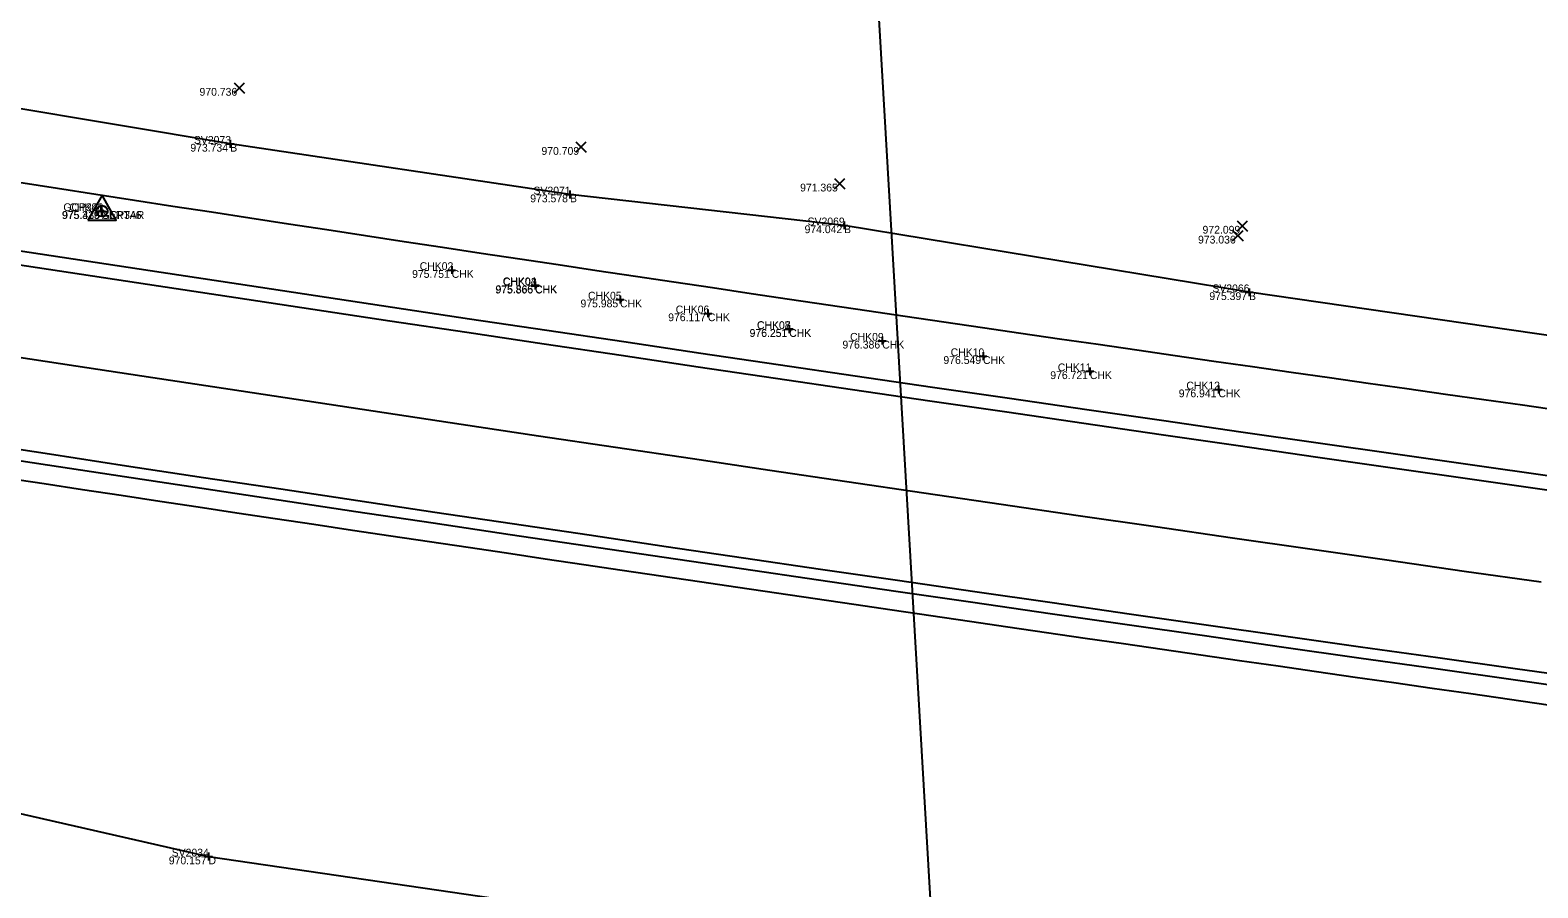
# Model space of a CAD drawing. Extents: x 2065431 to 2068157, y 709104 to 709719.
# Drawn here: x 2066286.8 to 2066480.2, y 709483.7 to 709593.7 of the extents above; entities that cross this region are included whole.
import ezdxf

# ---------------------------------------------------------------- set-up
doc = ezdxf.new("R2010")
doc.units = 0
for name, color, linetype in [('DR_X_Storm_Sewer', 7, 'Continuous'), ('PM_X_Edge_Line', 7, 'Continuous'), ('PM_X_Lane_Line', 7, 'Continuous'), ('PV_X_EOP', 7, 'Continuous'), ('PV_X_Shoulder_Rumble_Strip', 7, 'Continuous'), ('RS_Raster1', 7, 'Continuous'), ('RW_X_CL_100_Bearings', 7, 'Continuous'), ('RW_X_Fee_WL', 7, 'Continuous'), ('SV_P_Aerial_Targets', 7, 'Continuous'), ('SV_X_Break_Lines', 7, 'Continuous'), ('SV_X_Mon_Cells_Found', 7, 'Continuous'), ('SV_X_Text_Elevation', 7, 'Continuous'), ('SV_X_Text_Name', 7, 'Continuous')]:
    doc.layers.add(name, color=color, linetype=linetype)

msp = doc.modelspace()

# ---------------------------------------------------------------- linework, layer by layer
at = {"layer": 'DR_X_Storm_Sewer'}
msp.add_line((2066393.36, 709634.39), (2066412.21, 709311.61), dxfattribs=at)
at = {"layer": 'PM_X_Edge_Line'}
for points in [[(2066283.48, 709563.93), (2066293.37, 709562.43), (2066303.26, 709560.93), (2066313.15, 709559.43), (2066323.03, 709557.95), (2066332.92, 709556.46), (2066342.81, 709554.98), (2066352.7, 709553.51), (2066362.6, 709552.04), (2066372.49, 709550.57), (2066382.38, 709549.11), (2066392.27, 709547.66), (2066402.17, 709546.2), (2066412.06, 709544.76), (2066421.96, 709543.32), (2066431.85, 709541.88), (2066441.75, 709540.45), (2066451.65, 709539.02), (2066461.55, 709537.6), (2066471.45, 709536.18), (2066481.35, 709534.77)], [(2066279.38, 709540.88), (2066289.26, 709539.37), (2066299.15, 709537.87), (2066309.04, 709536.37), (2066318.93, 709534.88), (2066328.81, 709533.39), (2066338.7, 709531.92), (2066348.6, 709530.44), (2066358.49, 709528.98), (2066368.38, 709527.51), (2066378.27, 709526.06), (2066388.17, 709524.61), (2066398.06, 709523.17), (2066407.96, 709521.73), (2066417.86, 709520.3), (2066427.76, 709518.88), (2066437.65, 709517.46), (2066447.55, 709516.05), (2066457.45, 709514.65), (2066467.36, 709513.25), (2066477.26, 709511.86), (2066487.16, 709510.47)]]:
    msp.add_lwpolyline(points, dxfattribs=at)
at = {"layer": 'PM_X_Lane_Line'}
msp.add_lwpolyline([(2066282.76, 709552.18), (2066292.65, 709550.67), (2066302.53, 709549.17), (2066312.42, 709547.67), (2066322.31, 709546.17), (2066332.2, 709544.68), (2066342.09, 709543.2), (2066351.98, 709541.72), (2066361.87, 709540.24), (2066371.76, 709538.78), (2066381.65, 709537.31), (2066391.54, 709535.85), (2066401.44, 709534.4), (2066411.33, 709532.95), (2066421.23, 709531.5), (2066431.12, 709530.07), (2066441.02, 709528.63), (2066450.92, 709527.2), (2066460.81, 709525.78), (2066470.71, 709524.36), (2066480.61, 709522.95)], dxfattribs=at)
at = {"layer": 'PV_X_EOP'}
for points in [[(2066285.33, 709574.24), (2066290.27, 709573.47), (2066295.21, 709572.7), (2066300.15, 709571.94), (2066305.09, 709571.18), (2066310.04, 709570.42), (2066314.98, 709569.66), (2066319.92, 709568.91), (2066324.86, 709568.15), (2066329.81, 709567.4), (2066334.75, 709566.65), (2066339.69, 709565.9), (2066344.64, 709565.15), (2066349.58, 709564.41), (2066354.53, 709563.66), (2066359.47, 709562.92), (2066364.42, 709562.18), (2066369.36, 709561.44), (2066374.31, 709560.71), (2066379.25, 709559.97), (2066384.2, 709559.24), (2066389.14, 709558.51), (2066394.09, 709557.78), (2066399.04, 709557.05), (2066403.99, 709556.33), (2066408.93, 709555.6), (2066413.88, 709554.88), (2066418.83, 709554.16), (2066423.78, 709553.44), (2066428.72, 709552.73), (2066433.67, 709552.01), (2066438.62, 709551.3), (2066443.57, 709550.59), (2066448.52, 709549.88), (2066453.47, 709549.17), (2066458.42, 709548.47), (2066463.37, 709547.76), (2066468.32, 709547.06), (2066473.27, 709546.36), (2066478.22, 709545.66), (2066483.17, 709544.96)], [(2066283.62, 709536.32), (2066288.56, 709535.57), (2066293.51, 709534.82), (2066298.45, 709534.07), (2066303.4, 709533.33), (2066308.34, 709532.58), (2066313.29, 709531.84), (2066318.23, 709531.1), (2066323.17, 709530.36), (2066328.12, 709529.62), (2066333.06, 709528.88), (2066338.01, 709528.14), (2066342.96, 709527.4), (2066347.9, 709526.67), (2066352.85, 709525.93), (2066357.79, 709525.2), (2066362.74, 709524.47), (2066367.68, 709523.74), (2066372.63, 709523.01), (2066377.58, 709522.28), (2066382.52, 709521.55), (2066387.47, 709520.82), (2066392.42, 709520.1), (2066397.37, 709519.37), (2066402.31, 709518.65), (2066407.26, 709517.92), (2066412.21, 709517.2), (2066417.16, 709516.48), (2066422.1, 709515.76), (2066427.05, 709515.04), (2066432, 709514.33), (2066436.95, 709513.61), (2066441.9, 709512.89), (2066446.85, 709512.18), (2066451.79, 709511.47), (2066456.74, 709510.76), (2066461.69, 709510.04), (2066466.64, 709509.33), (2066471.59, 709508.63), (2066476.54, 709507.92), (2066481.49, 709507.21)]]:
    msp.add_lwpolyline(points, dxfattribs=at)
at = {"layer": 'PV_X_Shoulder_Rumble_Strip'}
for points in [[(2066283.83, 709565.69), (2066293.72, 709564.18), (2066303.6, 709562.68), (2066313.49, 709561.19), (2066323.38, 709559.7), (2066333.27, 709558.21), (2066343.16, 709556.73), (2066353.05, 709555.26), (2066362.94, 709553.79), (2066372.83, 709552.32), (2066382.73, 709550.86), (2066392.62, 709549.41), (2066402.51, 709547.96), (2066412.41, 709546.52), (2066422.31, 709545.08), (2066432.2, 709543.65), (2066442.1, 709542.22), (2066452, 709540.8), (2066461.9, 709539.38), (2066471.8, 709537.97), (2066481.7, 709536.56)], [(2066279.12, 709539.47), (2066289.01, 709537.97), (2066298.9, 709536.47), (2066308.79, 709534.98), (2066318.68, 709533.49), (2066328.56, 709532.01), (2066338.46, 709530.53), (2066348.35, 709529.06), (2066358.24, 709527.6), (2066368.13, 709526.14), (2066378.02, 709524.68), (2066387.92, 709523.23), (2066397.81, 709521.79), (2066407.71, 709520.35), (2066417.61, 709518.92), (2066427.51, 709517.49), (2066437.4, 709516.07), (2066447.3, 709514.65), (2066457.2, 709513.24), (2066467.1, 709511.84), (2066477, 709510.43), (2066486.91, 709509.04)]]:
    msp.add_lwpolyline(points, dxfattribs=at)
at = {"layer": 'RS_Raster1'}
for p, q in [((2066311.95, 709579.16), (2066312.95, 709579.16)), ((2066312.45, 709579.66), (2066312.45, 709578.66)), ((2066312.45, 709579.16), (2066312.45, 709579.16)), ((2066355.53, 709572.66), (2066356.53, 709572.66)), ((2066356.03, 709573.16), (2066356.03, 709572.16)), ((2066356.03, 709572.66), (2066356.03, 709572.66)), ((2066295.94, 709571.03), (2066295.94, 709570.03)), ((2066295.44, 709570.53), (2066296.44, 709570.53)), ((2066295.94, 709570.53), (2066295.94, 709570.53)), ((2066390.69, 709568.7), (2066391.69, 709568.7)), ((2066391.19, 709569.2), (2066391.19, 709568.2)), ((2066391.19, 709568.7), (2066391.19, 709568.7)), ((2066340.36, 709562.97), (2066341.36, 709562.97)), ((2066340.86, 709563.47), (2066340.86, 709562.47)), ((2066340.86, 709562.97), (2066340.86, 709562.97)), ((2066351.05, 709560.96), (2066352.05, 709560.96)), ((2066351.06, 709561.02), (2066352.06, 709561.02)), ((2066351.55, 709561.46), (2066351.55, 709560.46)), ((2066351.55, 709560.96), (2066351.55, 709560.96)), ((2066351.56, 709561.52), (2066351.56, 709560.52)), ((2066351.56, 709561.02), (2066351.56, 709561.02)), ((2066361.95, 709559.18), (2066362.95, 709559.18)), ((2066362.45, 709559.68), (2066362.45, 709558.68)), ((2066362.45, 709559.18), (2066362.45, 709559.18)), ((2066442.63, 709560.12), (2066443.63, 709560.12)), ((2066443.13, 709560.62), (2066443.13, 709559.62)), ((2066443.13, 709560.12), (2066443.13, 709560.12)), ((2066373.22, 709557.41), (2066374.22, 709557.41)), ((2066373.72, 709557.91), (2066373.72, 709556.91)), ((2066373.72, 709557.41), (2066373.72, 709557.41)), ((2066383.65, 709555.41), (2066384.65, 709555.41)), ((2066383.65, 709555.38), (2066384.65, 709555.38)), ((2066384.15, 709555.91), (2066384.15, 709554.91)), ((2066384.15, 709555.88), (2066384.15, 709554.88)), ((2066384.15, 709555.41), (2066384.15, 709555.41)), ((2066384.15, 709555.38), (2066384.15, 709555.38)), ((2066395.58, 709553.9), (2066396.58, 709553.9)), ((2066396.08, 709554.4), (2066396.08, 709553.4)), ((2066396.08, 709553.9), (2066396.08, 709553.9)), ((2066408.51, 709551.92), (2066409.51, 709551.92)), ((2066409.01, 709552.42), (2066409.01, 709551.42)), ((2066409.01, 709551.92), (2066409.01, 709551.92)), ((2066422.22, 709549.98), (2066423.22, 709549.98)), ((2066422.72, 709550.48), (2066422.72, 709549.48)), ((2066422.72, 709549.98), (2066422.72, 709549.98)), ((2066438.7, 709547.65), (2066439.7, 709547.65)), ((2066439.2, 709548.15), (2066439.2, 709547.15)), ((2066439.2, 709547.65), (2066439.2, 709547.65)), ((2066309.16, 709487.73), (2066310.16, 709487.73)), ((2066309.66, 709488.23), (2066309.66, 709487.23)), ((2066309.66, 709487.73), (2066309.66, 709487.73))]:
    msp.add_line(p, q, dxfattribs=at)
at = {"layer": 'RW_X_CL_100_Bearings'}
for p, q in [((2066312.95, 709585.66), (2066314.28, 709587)), ((2066312.95, 709587), (2066314.28, 709585.66)), ((2066356.79, 709578.08), (2066358.12, 709579.42)), ((2066356.79, 709579.42), (2066358.12, 709578.08)), ((2066389.95, 709573.38), (2066391.29, 709574.72)), ((2066389.95, 709574.72), (2066391.29, 709573.38)), ((2066441.59, 709567.97), (2066442.92, 709569.3)), ((2066441.59, 709569.3), (2066442.92, 709567.97)), ((2066441.03, 709566.7), (2066442.36, 709568.04)), ((2066441.03, 709568.04), (2066442.36, 709566.7))]:
    msp.add_line(p, q, dxfattribs=at)
at = {"layer": 'RW_X_Fee_WL'}
msp.add_lwpolyline([(2066146.22, 709516.28), (2066201.46, 709507.43), (2066256.41, 709499.89), (2066309.66, 709487.73), (2066371.95, 709478.62), (2066434.46, 709468.76), (2066488.47, 709461.11), (2066543.09, 709454.02), (2066597.26, 709445.92), (2066653.85, 709437.6), (2066711.8, 709429.8), (2066769.12, 709422.19), (2066823.53, 709415.48), (2066878.43, 709408.48), (2066947.7, 709399.97)], dxfattribs=at)
at = {"layer": 'SV_P_Aerial_Targets'}
msp.add_lwpolyline([(2066294.2, 709569.37), (2066297.8, 709569.37), (2066296, 709572.59)], close=True, dxfattribs=at)
for radius in [0.7, 0.16]:
    msp.add_circle((2066296, 709570.53), radius, dxfattribs=at)
at = {"layer": 'SV_X_Break_Lines'}
msp.add_lwpolyline([(2066577.27, 709544.99), (2066531.19, 709548.83), (2066485.96, 709553.92), (2066443.13, 709560.12), (2066391.19, 709568.7), (2066356.03, 709572.66), (2066312.45, 709579.16), (2066268.38, 709586.52), (2066230.11, 709591.56)], dxfattribs=at)

# ---------------------------------------------------------------- texts
at = {"layer": 'SV_X_Mon_Cells_Found'}
for s, p in [('SV2073', (2066307.79, 709579.16)), ('SV2071', (2066351.35, 709572.66)), ('GCP346', (2066291.04, 709570.53)), ('CHK01', (2066291.82, 709570.53)), ('SV2069', (2066386.51, 709568.7)), ('CHK02', (2066336.75, 709562.97)), ('CHK04', (2066347.4, 709561.02)), ('CHK03', (2066347.45, 709560.96)), ('SV2066', (2066438.43, 709560.12)), ('CHK05', (2066358.34, 709559.18)), ('CHK06', (2066369.59, 709557.41)), ('CHK08', (2066380.01, 709555.41)), ('CHK07', (2066380.02, 709555.38)), ('CHK09', (2066391.96, 709553.9)), ('CHK10', (2066404.86, 709551.92)), ('CHK11', (2066418.6, 709549.98)), ('CHK12', (2066435.09, 709547.65)), ('SV2034', (2066304.94, 709487.73))]:
    msp.add_text(s, height=1, dxfattribs=at).set_placement(p)
at = {"layer": 'SV_X_Text_Elevation'}
for s, p in [('B', (2066312.45, 709578.16)), ('B', (2066356.03, 709571.66)), ('GCP346', (2066295.94, 709569.53)), ('AERTAR', (2066296, 709569.53)), ('B', (2066391.19, 709567.7)), ('CHK', (2066340.86, 709561.97)), ('CHK', (2066351.56, 709560.02)), ('CHK', (2066351.55, 709559.96)), ('CHK', (2066362.45, 709558.18)), ('B', (2066443.13, 709559.12)), ('CHK', (2066373.72, 709556.41)), ('CHK', (2066384.15, 709554.41)), ('CHK', (2066384.15, 709554.38)), ('CHK', (2066396.08, 709552.9)), ('CHK', (2066409.01, 709550.92)), ('CHK', (2066422.72, 709548.98)), ('CHK', (2066439.2, 709546.65)), ('D', (2066309.66, 709486.73))]:
    msp.add_text(s, height=1, dxfattribs=at).set_placement(p)
at = {"layer": 'SV_X_Text_Name'}
for s, p in [('970.736', (2066308.51, 709585.33)), ('973.734', (2066307.33, 709578.16)), ('970.709', (2066352.37, 709577.75)), ('973.578', (2066350.93, 709571.66)), ('971.365', (2066385.55, 709573.05)), ('975.319', (2066290.85, 709569.53)), ('975.438', (2066290.9, 709569.53)), ('974.042', (2066386.12, 709567.7)), ('973.036', (2066436.59, 709566.37)), ('972.099', (2066437.17, 709567.64)), ('975.751', (2066335.78, 709561.97)), ('975.866', (2066346.45, 709559.96)), ('975.865', (2066346.49, 709560.02)), ('975.985', (2066357.38, 709558.18)), ('975.397', (2066438.04, 709559.12)), ('976.117', (2066368.63, 709556.41)), ('976.251', (2066379.07, 709554.41)), ('976.251', (2066379.07, 709554.38)), ('976.386', (2066390.98, 709552.9)), ('976.549', (2066403.93, 709550.92)), ('976.721', (2066417.64, 709548.98)), ('976.941', (2066434.12, 709546.65)), ('970.157', (2066304.57, 709486.73))]:
    msp.add_text(s, height=1, dxfattribs=at).set_placement(p)

doc.saveas('drawing.dxf')
